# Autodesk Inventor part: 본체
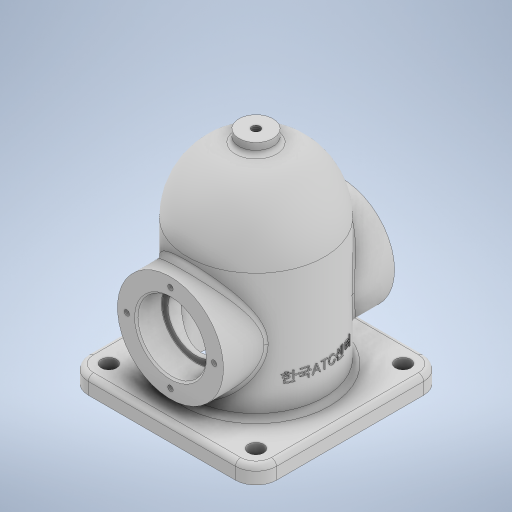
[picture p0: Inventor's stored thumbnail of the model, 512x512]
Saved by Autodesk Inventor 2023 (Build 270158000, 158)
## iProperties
Created: 2025-04
Part Number: 본체
Material: 일반
Document SubType Name: Modeling
Designer: User
Density: 1 g/cm^3
Appearance: 기본값
Author: User
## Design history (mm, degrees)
sketch "스케치1"
  geometry: L1 (0, -43.4)-(0, 43.4) reference; L2 (-43.4, 0)-(43.4, 0) reference; C1 r 31 at (0, 0); 1 further point
  constraints: 1 centre point, 1 coincident
  dimensions: "d0" = 62 diameter of C1
extrude "돌출1" new body sketch "스케치1" stored distance "d1" = 100; taper "d2" = 0 deg
node "작업 평면1"
sketch "스케치2"
  geometry: L1 (-55, 55)-(55, 55); L2 (55, 55)-(55, -55); L3 (55, -55)-(-55, -55); L4 (-55, -55)-(-55, 55); L5 (-55, 55)-(55, -55); L6 (55, 55)-(-55, -55); 1 further point
  constraints: 12 end point, 2 midpoint, 2 parallel, 1 horizontal, 1 perpendicular
  dimensions: "d4" = 110 distance of L3.end L1.start; "d5" = 110 distance of L2.end L3.end
extrude "돌출2" join sketch "스케치2" distance "d6" = 10; taper "d7" = 0 deg
sketch "스케치3"
  geometry: C1 r 40 at (0, 0); 1 further point
  constraints: 1 centre point, 1 coincident
  dimensions: "d8" = 80 diameter of C1
extrude "돌출3" join sketch "스케치3" distance "d9" = 84; taper "d10" = 0 deg
sketch "스케치4"
  geometry: L1 (-64.8, 0)-(52.8, 0) reference; L2 (0, -77)-(0, 77) reference; L3 (36, -40)-(36, 40) reference; L4 (36, -40)-(36, 0); L5 (36, 0)-(76, 0); A1 r 40 centre (36, 0) between (36, -40) and (76, 0); 2 further points
  constraints: 4 end point, 2 collinear, 2 point on circle, 1 centre point, 1 midpoint, 1 point on line
  dimensions: "d11" = 40 radius of A1
revolve "회전1" sketch "스케치4" stored, may be unused: angle "d12" = 360 deg
sketch "스케치5"
  geometry: C1 r 10 at (0, 0); 1 further point
  constraints: 1 centre point, 1 coincident
  dimensions: "d13" = 20 diameter of C1
extrude "돌출4" join sketch "스케치5" distance "d14" = 129; taper "d15" = 0 deg
sketch "스케치6"
  geometry: L1 (-73.8, 0)-(106.8, 0) reference; L2 (0, -77)-(0, 77) reference; L3 (36, -40)-(36, 40) reference; L4 (68, 0)-(-48, 0); L5 (-48, -55)-(-48, 55) reference; L6 (36, -32)-(-48, -32); L7 (-48, -32)-(-48, 0); A1 r 32 centre (36, 0) between (36, -32) and (68, 0); 2 further points
  constraints: 6 end point, 2 midpoint, 2 point on circle, 2 point on line, 1 centre point, 1 horizontal, 1 perpendicular
  dimensions: "d16" = 32 radius of A1
revolve "회전2" sketch "스케치6" stored, may be unused: angle "d17" = 360 deg
sketch "스케치7"
  geometry: L1 (-73.8, 0)-(106.8, 0) reference; L2 (0, -77)-(0, 77) reference; L3 (31, 50)-(-31, 50) reference; L4 (0, 50)-(20, 50); L5 (20, 50)-(20, 35); L6 (20, 35)-(0, 35); L7 (0, 35)-(0, 50); L8 (0, 35)-(16.5, 35); L9 (16.5, 35)-(16.5, -35); L10 (16.5, -35)-(0, -35); L11 (0, -35)-(0, 35); L12 (-31, -50)-(31, -50) reference; L13 (0, -35)-(20, -35); L14 (20, -35)-(20, -50); L15 (20, -50)-(0, -50); L16 (0, -50)-(0, -35); 5 further points
  constraints: 24 end point, 6 parallel, 4 symmetric about line, 3 horizontal, 3 perpendicular, 1 midpoint, 1 point on line
  dimensions: "d18" = 40 diameter of L4.end L2; "d19" = 33 diameter of L8.end L2; "d20" = 15 distance of L4.end L5.end
revolve "회전3" sketch "스케치7" stored, may be unused: angle "d21" = 360 deg
sketch "스케치8"
  geometry: L1 (-77, 0)-(77, 0) reference; L2 (0, -73.8)-(0, 106.8) reference; 2 further points
  constraints: 1 point on line
  dimensions: "d22" = 25.5 distance of point (0, 0) point (0, 25.5)
hole "구멍1" sketch "스케치8" at (0, 25.5) diameter "d23" = 3.242; stored, may be unused: countersink angle "d27" = 90 deg, drill point angle "d29" = 118 deg; dims "d24" = 8, "d25" = 4, "d26" = 2, "d28" = 10
sketch "스케치9"
  geometry: L1 (43, 43)-(-43, 43); L2 (-43, 43)-(-43, -43); L3 (-43, -43)-(43, -43); L4 (43, -43)-(43, 43); L5 (43, 43)-(-43, -43); L6 (-43, 43)-(43, -43); L7 (0, -77)-(0, 77) reference; L8 (-77, 0)-(77, 0) reference; C1 r 4.5 at (43, 43); C2 r 4.5 at (43, -43); C3 r 4.5 at (-43, 43); C4 r 4.5 at (-43, -43); 1 further point
  constraints: 12 end point, 4 centre point, 3 symmetric about line, 2 midpoint, 2 parallel, 1 coincident, 1 horizontal, 1 perpendicular, 3 other
  dimensions: "d33" = 86 distance of L3.end L1.start; "d34" = 86 distance of L2.end L3.end; "d35" = 9 diameter of C1
extrude "돌출5" cut sketch "스케치9" distance "d36" = 10; taper "d37" = 0 deg
sketch "스케치10"
  geometry: 1 further point
hole "구멍2" sketch "스케치10" at (0, 0) diameter "d38" = 4.917; stored, may be unused: countersink angle "d42" = 90 deg, drill point angle "d44" = 0 deg; dims "d39" = 20, "d40" = 4, "d41" = 2, "d43" = 25
chamfer "모따기1" distance "d45" = 1; stored, may be unused: second distance "d46" = 2, angle "d47" = 45 deg
fillet "모깎기1" dims "d48" = 12
fillet "모깎기2" dims "d49" = 0.3
fillet "모깎기3" dims "d50" = 3
fillet "모깎기4" dims "d51" = 3
node "작업 평면2"
sketch "스케치11"
  geometry: L1 (-73.8, 0)-(106.8, 0) reference; L2 (0, -77)-(0, 77) reference; L3 (-48, 43)-(-48, -43) reference; 2 further points
  constraints: 1 point on line, 1 other
  dimensions: "d53" = 30 distance from line of L3 point (-18, 0)
feature "엠보싱1" sketch "스케치11" dims "d54" = 0.5, "d55" = 0
node "솔리드1"
pattern_circular "원형 패턴1" dims angle "d31" = 360 deg
mirror "미러1"
feature "A9D066F2-1C7D-4E18-AEED-F7BC21143FA4" dims "d23" = 3.242, "d24" = 8, "d25" = 4, "d26" = 2, "d27" = 90 deg, "d28" = 10, "d29" = 118 deg
other parameters: "d3" = -48
